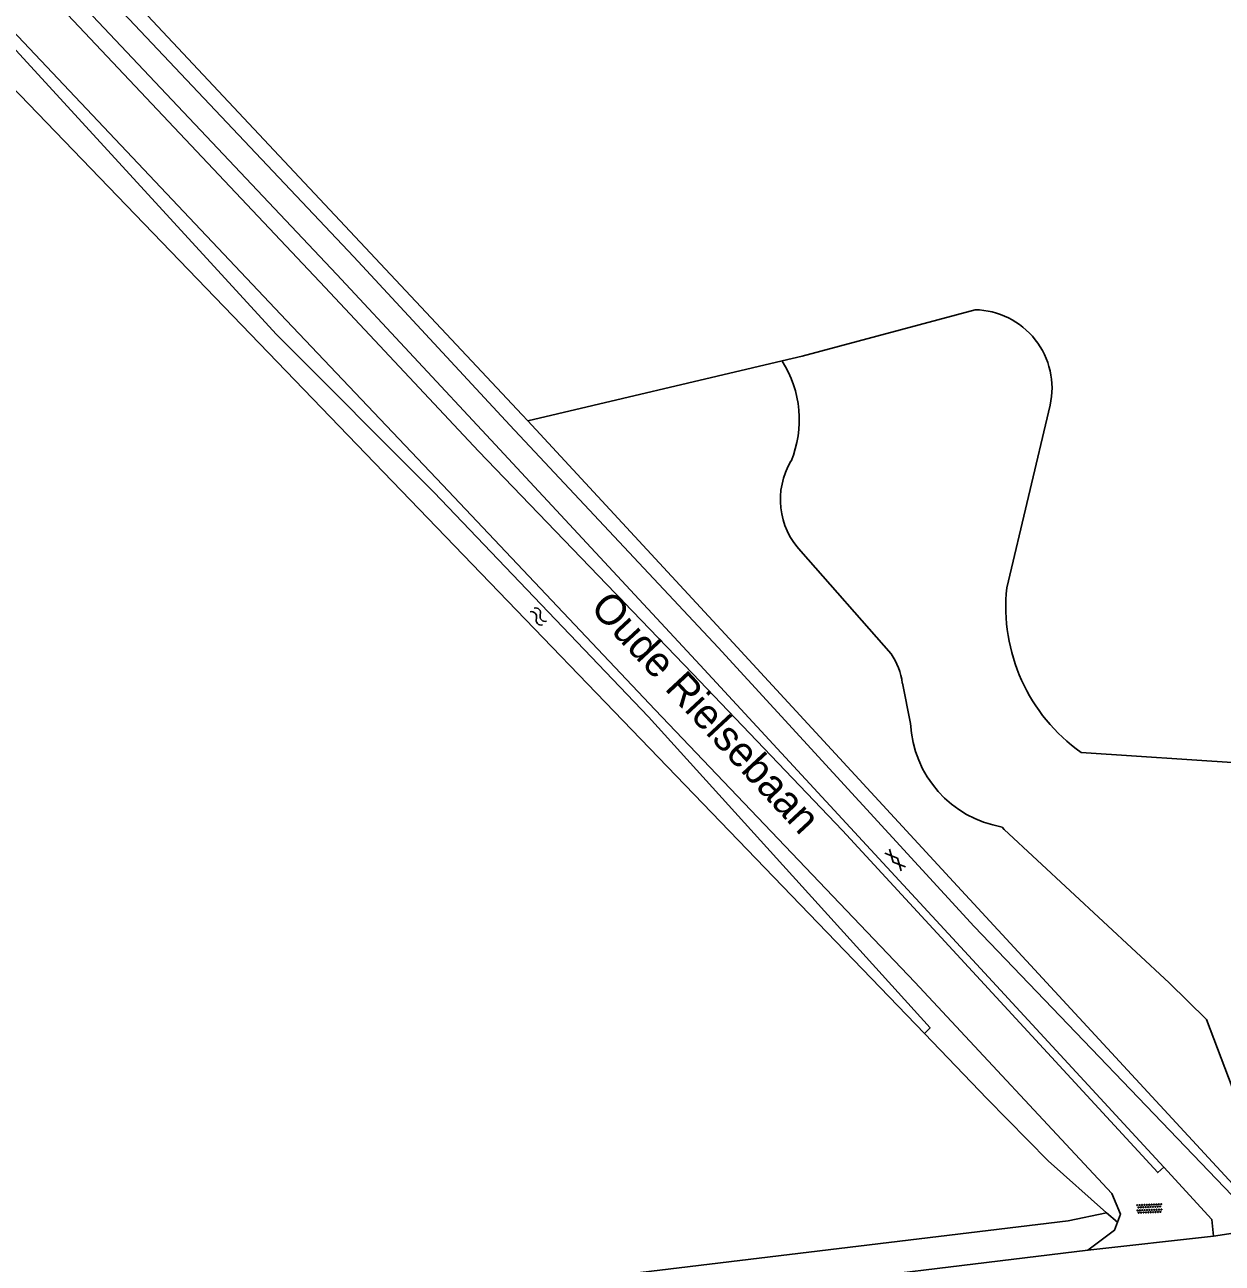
# Model space of a CAD drawing. Extents: x 126000 to 131009, y 393000 to 395500.
# Drawn here: x 129972.7 to 130072.2, y 394625.1 to 394728 of the extents above; entities that cross this region are included whole.
import ezdxf

# ---------------------------------------------------------------- set-up
doc = ezdxf.new("R2010")
doc.units = 0
for name, color, linetype in [('gg-afsc-draadraster', 7, 'Continuous'), ('gg-anno-openbare ruimte label', 7, 'Continuous'), ('gg-knt-onverhard', 7, 'Continuous'), ('gg-knt-verharding', 7, 'Continuous'), ('gg-kntw-bovenkant insteek waterloop', 7, 'Continuous'), ('gt-grn-groengrens', 7, 'Continuous'), ('gt-grn-groengrens NZ', 7, 'Continuous'), ('gt-grn-weggrens', 7, 'Continuous'), ('gt-symb-gesloten verharding', 7, 'Continuous'), ('gt-symb-overige verharding', 7, 'Continuous'), ('gt-symb-watersymbool', 7, 'Continuous')]:
    doc.layers.add(name, color=color, linetype=linetype)

# ---------------------------------------------------------------- blocks, each defined once
blk = doc.blocks.new('gt0-GESVH1')
at = {"layer": 'gt-symb-gesloten verharding'}
for p, q in [((-0.99, -0.26), (0.01, 0.24)), ((0.01, -0.26), (-0.99, 0.24)), ((0.01, 0.24), (1.01, -0.26)), ((1.01, 0.24), (0.01, -0.26))]:
    blk.add_line(p, q, dxfattribs=at)
blk = doc.blocks.new('gt0-OVH')
at = {"layer": 'gt-symb-overige verharding'}
for points in [[(-0.97, 0.3), (-0.97, 0.31), (-0.96, 0.32), (-0.97, 0.33), (-0.97, 0.34), (-0.98, 0.35), (-0.99, 0.35), (-1, 0.36), (-1.01, 0.35), (-1.02, 0.35), (-1.03, 0.34), (-1.03, 0.33), (-1.04, 0.32), (-1.03, 0.31), (-1.03, 0.3), (-1.02, 0.29), (-1.01, 0.29), (-1, 0.28), (-0.99, 0.29), (-0.98, 0.29)], [(-0.87, 0.11), (-0.87, 0.12), (-0.86, 0.13), (-0.87, 0.14), (-0.87, 0.15), (-0.88, 0.16), (-0.89, 0.16), (-0.9, 0.16), (-0.91, 0.16), (-0.92, 0.16), (-0.93, 0.15), (-0.93, 0.14), (-0.94, 0.13), (-0.93, 0.12), (-0.93, 0.11), (-0.92, 0.1), (-0.91, 0.09), (-0.9, 0.09), (-0.89, 0.09), (-0.88, 0.1)], [(-0.77, 0.3), (-0.77, 0.31), (-0.76, 0.32), (-0.77, 0.33), (-0.77, 0.34), (-0.78, 0.35), (-0.79, 0.35), (-0.8, 0.36), (-0.81, 0.35), (-0.82, 0.35), (-0.83, 0.34), (-0.83, 0.33), (-0.84, 0.32), (-0.83, 0.31), (-0.83, 0.3), (-0.82, 0.29), (-0.81, 0.29), (-0.8, 0.28), (-0.79, 0.29), (-0.78, 0.29)], [(-0.67, 0.11), (-0.67, 0.12), (-0.66, 0.13), (-0.67, 0.14), (-0.67, 0.15), (-0.68, 0.16), (-0.69, 0.16), (-0.7, 0.16), (-0.71, 0.16), (-0.72, 0.16), (-0.73, 0.15), (-0.73, 0.14), (-0.74, 0.13), (-0.73, 0.12), (-0.73, 0.11), (-0.72, 0.1), (-0.71, 0.09), (-0.7, 0.09), (-0.69, 0.09), (-0.68, 0.1)], [(-0.57, 0.3), (-0.57, 0.31), (-0.56, 0.32), (-0.57, 0.33), (-0.57, 0.34), (-0.58, 0.35), (-0.59, 0.35), (-0.6, 0.36), (-0.61, 0.35), (-0.62, 0.35), (-0.63, 0.34), (-0.63, 0.33), (-0.64, 0.32), (-0.63, 0.31), (-0.63, 0.3), (-0.62, 0.29), (-0.61, 0.29), (-0.6, 0.28), (-0.59, 0.29), (-0.58, 0.29)], [(-0.47, 0.11), (-0.47, 0.12), (-0.46, 0.13), (-0.47, 0.14), (-0.47, 0.15), (-0.48, 0.16), (-0.49, 0.16), (-0.5, 0.16), (-0.51, 0.16), (-0.52, 0.16), (-0.53, 0.15), (-0.53, 0.14), (-0.54, 0.13), (-0.53, 0.12), (-0.53, 0.11), (-0.52, 0.1), (-0.51, 0.09), (-0.5, 0.09), (-0.49, 0.09), (-0.48, 0.1)], [(-0.37, 0.3), (-0.37, 0.31), (-0.36, 0.32), (-0.37, 0.33), (-0.37, 0.34), (-0.38, 0.35), (-0.39, 0.35), (-0.4, 0.36), (-0.41, 0.35), (-0.42, 0.35), (-0.43, 0.34), (-0.43, 0.33), (-0.44, 0.32), (-0.43, 0.31), (-0.43, 0.3), (-0.42, 0.29), (-0.41, 0.29), (-0.4, 0.28), (-0.39, 0.29), (-0.38, 0.29)], [(-0.27, 0.11), (-0.27, 0.12), (-0.26, 0.13), (-0.27, 0.14), (-0.27, 0.15), (-0.28, 0.16), (-0.29, 0.16), (-0.3, 0.16), (-0.31, 0.16), (-0.32, 0.16), (-0.33, 0.15), (-0.33, 0.14), (-0.34, 0.13), (-0.33, 0.12), (-0.33, 0.11), (-0.32, 0.1), (-0.31, 0.09), (-0.3, 0.09), (-0.29, 0.09), (-0.28, 0.1)], [(-0.17, 0.3), (-0.17, 0.31), (-0.16, 0.32), (-0.17, 0.33), (-0.17, 0.34), (-0.18, 0.35), (-0.19, 0.35), (-0.2, 0.36), (-0.21, 0.35), (-0.22, 0.35), (-0.23, 0.34), (-0.23, 0.33), (-0.24, 0.32), (-0.23, 0.31), (-0.23, 0.3), (-0.22, 0.29), (-0.21, 0.29), (-0.2, 0.28), (-0.19, 0.29), (-0.18, 0.29)], [(-0.07, 0.11), (-0.07, 0.12), (-0.06, 0.13), (-0.07, 0.14), (-0.07, 0.15), (-0.08, 0.16), (-0.09, 0.16), (-0.1, 0.16), (-0.11, 0.16), (-0.12, 0.16), (-0.13, 0.15), (-0.13, 0.14), (-0.14, 0.13), (-0.13, 0.12), (-0.13, 0.11), (-0.12, 0.1), (-0.11, 0.09), (-0.1, 0.09), (-0.09, 0.09), (-0.08, 0.1)], [(0.03, 0.3), (0.03, 0.31), (0.04, 0.32), (0.03, 0.33), (0.03, 0.34), (0.02, 0.35), (0.01, 0.35), (0, 0.36), (-0.01, 0.35), (-0.02, 0.35), (-0.03, 0.34), (-0.03, 0.33), (-0.04, 0.32), (-0.03, 0.31), (-0.03, 0.3), (-0.02, 0.29), (-0.01, 0.29), (0, 0.28), (0.01, 0.29), (0.02, 0.29)], [(0.13, 0.11), (0.13, 0.12), (0.14, 0.13), (0.13, 0.14), (0.13, 0.15), (0.12, 0.16), (0.11, 0.16), (0.1, 0.16), (0.09, 0.16), (0.08, 0.16), (0.07, 0.15), (0.07, 0.14), (0.06, 0.13), (0.07, 0.12), (0.07, 0.11), (0.08, 0.1), (0.09, 0.09), (0.1, 0.09), (0.11, 0.09), (0.12, 0.1)], [(0.23, 0.3), (0.23, 0.31), (0.24, 0.32), (0.23, 0.33), (0.23, 0.34), (0.22, 0.35), (0.21, 0.35), (0.2, 0.36), (0.19, 0.35), (0.18, 0.35), (0.17, 0.34), (0.17, 0.33), (0.16, 0.32), (0.17, 0.31), (0.17, 0.3), (0.18, 0.29), (0.19, 0.29), (0.2, 0.28), (0.21, 0.29), (0.22, 0.29)], [(0.33, 0.11), (0.33, 0.12), (0.34, 0.13), (0.33, 0.14), (0.33, 0.15), (0.32, 0.16), (0.31, 0.16), (0.3, 0.16), (0.29, 0.16), (0.28, 0.16), (0.27, 0.15), (0.27, 0.14), (0.26, 0.13), (0.27, 0.12), (0.27, 0.11), (0.28, 0.1), (0.29, 0.09), (0.3, 0.09), (0.31, 0.09), (0.32, 0.1)], [(0.43, 0.3), (0.43, 0.31), (0.44, 0.32), (0.43, 0.33), (0.43, 0.34), (0.42, 0.35), (0.41, 0.35), (0.4, 0.36), (0.39, 0.35), (0.38, 0.35), (0.37, 0.34), (0.37, 0.33), (0.36, 0.32), (0.37, 0.31), (0.37, 0.3), (0.38, 0.29), (0.39, 0.29), (0.4, 0.28), (0.41, 0.29), (0.42, 0.29)], [(0.53, 0.11), (0.53, 0.12), (0.54, 0.13), (0.53, 0.14), (0.53, 0.15), (0.52, 0.16), (0.51, 0.16), (0.5, 0.16), (0.49, 0.16), (0.48, 0.16), (0.47, 0.15), (0.47, 0.14), (0.46, 0.13), (0.47, 0.12), (0.47, 0.11), (0.48, 0.1), (0.49, 0.09), (0.5, 0.09), (0.51, 0.09), (0.52, 0.1)], [(0.63, 0.3), (0.63, 0.31), (0.64, 0.32), (0.63, 0.33), (0.63, 0.34), (0.62, 0.35), (0.61, 0.35), (0.6, 0.36), (0.59, 0.35), (0.58, 0.35), (0.57, 0.34), (0.57, 0.33), (0.56, 0.32), (0.57, 0.31), (0.57, 0.3), (0.58, 0.29), (0.59, 0.29), (0.6, 0.28), (0.61, 0.29), (0.62, 0.29)], [(0.73, 0.11), (0.73, 0.12), (0.74, 0.13), (0.73, 0.14), (0.73, 0.15), (0.72, 0.16), (0.71, 0.16), (0.7, 0.16), (0.69, 0.16), (0.68, 0.16), (0.67, 0.15), (0.67, 0.14), (0.66, 0.13), (0.67, 0.12), (0.67, 0.11), (0.68, 0.1), (0.69, 0.09), (0.7, 0.09), (0.71, 0.09), (0.72, 0.1)], [(0.83, 0.3), (0.83, 0.31), (0.84, 0.32), (0.83, 0.33), (0.83, 0.34), (0.82, 0.35), (0.81, 0.35), (0.8, 0.36), (0.79, 0.35), (0.78, 0.35), (0.77, 0.34), (0.77, 0.33), (0.76, 0.32), (0.77, 0.31), (0.77, 0.3), (0.78, 0.29), (0.79, 0.29), (0.8, 0.28), (0.81, 0.29), (0.82, 0.29)], [(0.93, 0.11), (0.93, 0.12), (0.94, 0.13), (0.93, 0.14), (0.93, 0.15), (0.92, 0.16), (0.91, 0.16), (0.9, 0.16), (0.89, 0.16), (0.88, 0.16), (0.87, 0.15), (0.87, 0.14), (0.86, 0.13), (0.87, 0.12), (0.87, 0.11), (0.88, 0.1), (0.89, 0.09), (0.9, 0.09), (0.91, 0.09), (0.92, 0.1)], [(1.03, 0.3), (1.03, 0.31), (1.04, 0.32), (1.03, 0.33), (1.03, 0.34), (1.02, 0.35), (1.01, 0.35), (1, 0.36), (0.99, 0.35), (0.98, 0.35), (0.97, 0.34), (0.97, 0.33), (0.96, 0.32), (0.97, 0.31), (0.97, 0.3), (0.98, 0.29), (0.99, 0.29), (1, 0.28), (1.01, 0.29), (1.02, 0.29)], [(-0.97, -0.14), (-0.97, -0.13), (-0.96, -0.12), (-0.97, -0.11), (-0.97, -0.1), (-0.98, -0.09), (-0.99, -0.09), (-1, -0.08), (-1.01, -0.09), (-1.02, -0.09), (-1.03, -0.1), (-1.03, -0.11), (-1.04, -0.12), (-1.03, -0.13), (-1.03, -0.14), (-1.02, -0.15), (-1.01, -0.15), (-1, -0.16), (-0.99, -0.15), (-0.98, -0.15)], [(-0.87, -0.33), (-0.87, -0.32), (-0.86, -0.31), (-0.87, -0.3), (-0.87, -0.29), (-0.88, -0.28), (-0.89, -0.28), (-0.9, -0.28), (-0.91, -0.28), (-0.92, -0.28), (-0.93, -0.29), (-0.93, -0.3), (-0.94, -0.31), (-0.93, -0.32), (-0.93, -0.33), (-0.92, -0.34), (-0.91, -0.35), (-0.9, -0.35), (-0.89, -0.35), (-0.88, -0.34)], [(-0.77, -0.14), (-0.77, -0.13), (-0.76, -0.12), (-0.77, -0.11), (-0.77, -0.1), (-0.78, -0.09), (-0.79, -0.09), (-0.8, -0.08), (-0.81, -0.09), (-0.82, -0.09), (-0.83, -0.1), (-0.83, -0.11), (-0.84, -0.12), (-0.83, -0.13), (-0.83, -0.14), (-0.82, -0.15), (-0.81, -0.15), (-0.8, -0.16), (-0.79, -0.15), (-0.78, -0.15)], [(-0.67, -0.33), (-0.67, -0.32), (-0.66, -0.31), (-0.67, -0.3), (-0.67, -0.29), (-0.68, -0.28), (-0.69, -0.28), (-0.7, -0.28), (-0.71, -0.28), (-0.72, -0.28), (-0.73, -0.29), (-0.73, -0.3), (-0.74, -0.31), (-0.73, -0.32), (-0.73, -0.33), (-0.72, -0.34), (-0.71, -0.35), (-0.7, -0.35), (-0.69, -0.35), (-0.68, -0.34)], [(-0.57, -0.14), (-0.57, -0.13), (-0.56, -0.12), (-0.57, -0.11), (-0.57, -0.1), (-0.58, -0.09), (-0.59, -0.09), (-0.6, -0.08), (-0.61, -0.09), (-0.62, -0.09), (-0.63, -0.1), (-0.63, -0.11), (-0.64, -0.12), (-0.63, -0.13), (-0.63, -0.14), (-0.62, -0.15), (-0.61, -0.15), (-0.6, -0.16), (-0.59, -0.15), (-0.58, -0.15)], [(-0.47, -0.33), (-0.47, -0.32), (-0.46, -0.31), (-0.47, -0.3), (-0.47, -0.29), (-0.48, -0.28), (-0.49, -0.28), (-0.5, -0.28), (-0.51, -0.28), (-0.52, -0.28), (-0.53, -0.29), (-0.53, -0.3), (-0.54, -0.31), (-0.53, -0.32), (-0.53, -0.33), (-0.52, -0.34), (-0.51, -0.35), (-0.5, -0.35), (-0.49, -0.35), (-0.48, -0.34)], [(-0.37, -0.14), (-0.37, -0.13), (-0.36, -0.12), (-0.37, -0.11), (-0.37, -0.1), (-0.38, -0.09), (-0.39, -0.09), (-0.4, -0.08), (-0.41, -0.09), (-0.42, -0.09), (-0.43, -0.1), (-0.43, -0.11), (-0.44, -0.12), (-0.43, -0.13), (-0.43, -0.14), (-0.42, -0.15), (-0.41, -0.15), (-0.4, -0.16), (-0.39, -0.15), (-0.38, -0.15)], [(-0.27, -0.33), (-0.27, -0.32), (-0.26, -0.31), (-0.27, -0.3), (-0.27, -0.29), (-0.28, -0.28), (-0.29, -0.28), (-0.3, -0.28), (-0.31, -0.28), (-0.32, -0.28), (-0.33, -0.29), (-0.33, -0.3), (-0.34, -0.31), (-0.33, -0.32), (-0.33, -0.33), (-0.32, -0.34), (-0.31, -0.35), (-0.3, -0.35), (-0.29, -0.35), (-0.28, -0.34)], [(-0.17, -0.14), (-0.17, -0.13), (-0.16, -0.12), (-0.17, -0.11), (-0.17, -0.1), (-0.18, -0.09), (-0.19, -0.09), (-0.2, -0.08), (-0.21, -0.09), (-0.22, -0.09), (-0.23, -0.1), (-0.23, -0.11), (-0.24, -0.12), (-0.23, -0.13), (-0.23, -0.14), (-0.22, -0.15), (-0.21, -0.15), (-0.2, -0.16), (-0.19, -0.15), (-0.18, -0.15)], [(-0.07, -0.33), (-0.07, -0.32), (-0.06, -0.31), (-0.07, -0.3), (-0.07, -0.29), (-0.08, -0.28), (-0.09, -0.28), (-0.1, -0.28), (-0.11, -0.28), (-0.12, -0.28), (-0.13, -0.29), (-0.13, -0.3), (-0.14, -0.31), (-0.13, -0.32), (-0.13, -0.33), (-0.12, -0.34), (-0.11, -0.35), (-0.1, -0.35), (-0.09, -0.35), (-0.08, -0.34)], [(0.03, -0.14), (0.03, -0.13), (0.04, -0.12), (0.03, -0.11), (0.03, -0.1), (0.02, -0.09), (0.01, -0.09), (0, -0.08), (-0.01, -0.09), (-0.02, -0.09), (-0.03, -0.1), (-0.03, -0.11), (-0.04, -0.12), (-0.03, -0.13), (-0.03, -0.14), (-0.02, -0.15), (-0.01, -0.15), (0, -0.16), (0.01, -0.15), (0.02, -0.15)], [(0.13, -0.33), (0.13, -0.32), (0.14, -0.31), (0.13, -0.3), (0.13, -0.29), (0.12, -0.28), (0.11, -0.28), (0.1, -0.28), (0.09, -0.28), (0.08, -0.28), (0.07, -0.29), (0.07, -0.3), (0.06, -0.31), (0.07, -0.32), (0.07, -0.33), (0.08, -0.34), (0.09, -0.35), (0.1, -0.35), (0.11, -0.35), (0.12, -0.34)], [(0.23, -0.14), (0.23, -0.13), (0.24, -0.12), (0.23, -0.11), (0.23, -0.1), (0.22, -0.09), (0.21, -0.09), (0.2, -0.08), (0.19, -0.09), (0.18, -0.09), (0.17, -0.1), (0.17, -0.11), (0.16, -0.12), (0.17, -0.13), (0.17, -0.14), (0.18, -0.15), (0.19, -0.15), (0.2, -0.16), (0.21, -0.15), (0.22, -0.15)], [(0.33, -0.33), (0.33, -0.32), (0.34, -0.31), (0.33, -0.3), (0.33, -0.29), (0.32, -0.28), (0.31, -0.28), (0.3, -0.28), (0.29, -0.28), (0.28, -0.28), (0.27, -0.29), (0.27, -0.3), (0.26, -0.31), (0.27, -0.32), (0.27, -0.33), (0.28, -0.34), (0.29, -0.35), (0.3, -0.35), (0.31, -0.35), (0.32, -0.34)], [(0.43, -0.14), (0.43, -0.13), (0.44, -0.12), (0.43, -0.11), (0.43, -0.1), (0.42, -0.09), (0.41, -0.09), (0.4, -0.08), (0.39, -0.09), (0.38, -0.09), (0.37, -0.1), (0.37, -0.11), (0.36, -0.12), (0.37, -0.13), (0.37, -0.14), (0.38, -0.15), (0.39, -0.15), (0.4, -0.16), (0.41, -0.15), (0.42, -0.15)], [(0.53, -0.33), (0.53, -0.32), (0.54, -0.31), (0.53, -0.3), (0.53, -0.29), (0.52, -0.28), (0.51, -0.28), (0.5, -0.28), (0.49, -0.28), (0.48, -0.28), (0.47, -0.29), (0.47, -0.3), (0.46, -0.31), (0.47, -0.32), (0.47, -0.33), (0.48, -0.34), (0.49, -0.35), (0.5, -0.35), (0.51, -0.35), (0.52, -0.34)], [(0.63, -0.14), (0.63, -0.13), (0.64, -0.12), (0.63, -0.11), (0.63, -0.1), (0.62, -0.09), (0.61, -0.09), (0.6, -0.08), (0.59, -0.09), (0.58, -0.09), (0.57, -0.1), (0.57, -0.11), (0.56, -0.12), (0.57, -0.13), (0.57, -0.14), (0.58, -0.15), (0.59, -0.15), (0.6, -0.16), (0.61, -0.15), (0.62, -0.15)], [(0.73, -0.33), (0.73, -0.32), (0.74, -0.31), (0.73, -0.3), (0.73, -0.29), (0.72, -0.28), (0.71, -0.28), (0.7, -0.28), (0.69, -0.28), (0.68, -0.28), (0.67, -0.29), (0.67, -0.3), (0.66, -0.31), (0.67, -0.32), (0.67, -0.33), (0.68, -0.34), (0.69, -0.35), (0.7, -0.35), (0.71, -0.35), (0.72, -0.34)], [(0.83, -0.14), (0.83, -0.13), (0.84, -0.12), (0.83, -0.11), (0.83, -0.1), (0.82, -0.09), (0.81, -0.09), (0.8, -0.08), (0.79, -0.09), (0.78, -0.09), (0.77, -0.1), (0.77, -0.11), (0.76, -0.12), (0.77, -0.13), (0.77, -0.14), (0.78, -0.15), (0.79, -0.15), (0.8, -0.16), (0.81, -0.15), (0.82, -0.15)], [(0.93, -0.33), (0.93, -0.32), (0.94, -0.31), (0.93, -0.3), (0.93, -0.29), (0.92, -0.28), (0.91, -0.28), (0.9, -0.28), (0.89, -0.28), (0.88, -0.28), (0.87, -0.29), (0.87, -0.3), (0.86, -0.31), (0.87, -0.32), (0.87, -0.33), (0.88, -0.34), (0.89, -0.35), (0.9, -0.35), (0.91, -0.35), (0.92, -0.34)], [(1.03, -0.14), (1.03, -0.13), (1.04, -0.12), (1.03, -0.11), (1.03, -0.1), (1.02, -0.09), (1.01, -0.09), (1, -0.08), (0.99, -0.09), (0.98, -0.09), (0.97, -0.1), (0.97, -0.11), (0.96, -0.12), (0.97, -0.13), (0.97, -0.14), (0.98, -0.15), (0.99, -0.15), (1, -0.16), (1.01, -0.15), (1.02, -0.15)]]:
    blk.add_lwpolyline(points, close=True, dxfattribs=at)
blk = doc.blocks.new('gt0-WA')
at = {"layer": 'gt-symb-watersymbool'}
for centre, start, end in [((-0.32, 0.02), 28.0725, 151.9275), ((0.43, 0.42), 208.0725, 331.9275), ((-0.32, -0.43), 28.0725, 151.9275), ((0.43, -0.03), 208.0725, 331.9275)]:
    blk.add_arc(centre, 0.425, start, end, dxfattribs=at)

msp = doc.modelspace()

# ---------------------------------------------------------------- linework, layer by layer
at = {"layer": 'gg-afsc-draadraster'}
for points in [[(130047.44, 394644.17), (129928, 394768.1), (129919.81, 394776.58)], [(130014.47, 394695.08), (130014.01, 394695.59), (129982.87, 394728.78)], [(130075.1, 394629.46), (130050.19, 394656.42), (130031.21, 394677.01), (130014.47, 394695.08)], [(130047.44, 394644.17), (130052.66, 394638.75), (130057.74, 394633.58), (130062.59, 394629.25)], [(130062.59, 394629.25), (130059.39, 394628.6), (129969.94, 394617.79)]]:
    msp.add_lwpolyline(points, dxfattribs=at)
at = {"layer": 'gg-knt-onverhard'}
for points in [[(130063.49, 394628.48), (130063.74, 394629.15), (130063.01, 394630.86), (130046.64, 394648.43), (130025.07, 394671.07), (130007.4, 394689.76), (129994.42, 394703.43), (129970.68, 394728.56), (129953.58, 394747.04), (129931.14, 394770.8), (129920.15, 394783.82), (129902.47, 394802.96), (129885.37, 394821.38), (129867.49, 394840.47), (129851.12, 394858.48), (129848.86, 394860.54), (129846.38, 394862.09), (129844.24, 394863.22), (129842.88, 394863.87)], [(130067.33, 394633.05), (130066.84, 394632.61), (130040.63, 394661.04), (130028.16, 394674.08), (130010.38, 394692.58), (129997.63, 394706.17), (129973.91, 394731.34), (129956.53, 394749.57), (129934.46, 394773.89), (129922.75, 394786.23), (129905.18, 394805.79), (129888.03, 394823.96), (129870.13, 394843.16), (129851.53, 394862.63), (129852.16, 394863.16)], [(130061.02, 394626.17), (130063.24, 394627.82), (130063.49, 394628.48)]]:
    msp.add_lwpolyline(points, dxfattribs=at)
at = {"layer": 'gg-knt-verharding'}
for p, q in [((130061.02, 394626.17), (130071.48, 394627.31)), ((130012.58, 394620.28), (130061.02, 394626.17))]:
    msp.add_line(p, q, dxfattribs=at)
for points in [[(129852.67, 394868.04), (129852.55, 394867.77), (129852.53, 394866.31), (129853.59, 394864.52), (129865.73, 394851.71), (129890.08, 394825.88), (129907.16, 394807.68), (129925.24, 394788.47), (129936.89, 394776), (129959.08, 394752.22), (129976.51, 394733.6), (130000.01, 394708.71), (130012.98, 394694.73), (130030.31, 394676.24), (130051.58, 394653.06), (130074.32, 394629.35)], [(130042.3, 394660.18), (130028.8, 394674.77), (130011.4, 394693.51), (129998.61, 394707.24), (129975.01, 394732.26), (129935.35, 394774.59), (129923.76, 394787.01), (129905.67, 394806.29), (129888.66, 394824.46), (129864.32, 394850.26)], [(130067.33, 394633.05), (130050.1, 394651.74), (130042.3, 394660.18)], [(130071.48, 394627.31), (130071.33, 394628.72), (130067.33, 394633.05)]]:
    msp.add_lwpolyline(points, dxfattribs=at)
at = {"layer": 'gg-kntw-bovenkant insteek waterloop'}
msp.add_lwpolyline([(130047.44, 394644.17), (130047.91, 394644.63), (130024.51, 394670.5), (130006.66, 394689.15), (129993.6, 394702.28), (129953.01, 394746.53), (129930.23, 394769.98), (129919.18, 394782.99), (129901.45, 394801.74), (129884.29, 394820.33), (129866.34, 394839.2), (129849.05, 394856.6), (129846.71, 394854.4)], dxfattribs=at)
at = {"layer": 'gt-grn-groengrens'}
for p, q in [((130037.28, 394700.46), (130051.65, 394704.33)), ((130014.47, 394695.08), (130035.62, 394700.07)), ((130035.62, 394700.07), (130037.28, 394700.46)), ((130054.3, 394681.22), (130057.9, 394696.38)), ((130037.17, 394684.25), (130044.68, 394675.72)), ((130045.61, 394673.28), (130046.3, 394669.93)), ((130073.86, 394666.63), (130060.47, 394667.53)), ((130074.62, 394635.47), (130070.89, 394645.32))]:
    msp.add_line(p, q, dxfattribs=at)
msp.add_lwpolyline([(130053.9, 394661.33), (130054.07, 394661.13), (130067.79, 394648.37), (130070.89, 394645.32)], dxfattribs=at)
for centre, radius, start, end in [((130051.52, 394697.8), 6.53, 347.4936, 88.8845), ((130027.94, 394695.19), 9.1, 337.6309, 32.3774), ((130041.73, 394688.53), 6.26, 149.2775, 223.2028), ((130069.06, 394679.64), 14.85, 173.9245, 234.6445), ((130040.1, 394672.58), 5.55, 7.226, 34.516), ((130055.44, 394670.35), 9.15, 182.6468, 260.2992)]:
    msp.add_arc(centre, radius, start, end, dxfattribs=at)
at = {"layer": 'gt-grn-groengrens NZ'}
msp.add_line((130062.59, 394629.25), (130063.49, 394628.48), dxfattribs=at)
at = {"layer": 'gt-grn-weggrens'}
msp.add_line((130075.65, 394627.97), (130071.48, 394627.31), dxfattribs=at)

# ---------------------------------------------------------------- block references
at = {"layer": 'gt-symb-gesloten verharding', "rotation": -47.47195593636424}
msp.add_blockref('gt0-GESVH1', (130045.02, 394658.6), dxfattribs=at)
at = {"layer": 'gt-symb-overige verharding', "rotation": 2.2356368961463}
msp.add_blockref('gt0-OVH', (130066.14, 394629.62), dxfattribs=at)
at = {"layer": 'gt-symb-watersymbool', "rotation": -46.74307034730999}
msp.add_blockref('gt0-WA', (130015.32, 394678.87), dxfattribs=at)

# ---------------------------------------------------------------- texts
at = {"layer": 'gg-anno-openbare ruimte label'}
msp.add_text('Oude Rielsebaan', height=2.5, rotation=312.9, dxfattribs=at).set_placement((130019.58, 394679.48))

doc.saveas('drawing.dxf')
